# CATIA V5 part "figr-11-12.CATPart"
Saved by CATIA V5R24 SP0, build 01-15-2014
Part number: Part1
Bounding box of the stored display mesh (mm): x -10 to 5, y -10.258 to 7.91, z -1.851 to 2.054
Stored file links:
  D:\KAVITA\CATIA V5-6R2014 Project_ Kavita\CATIA V5-6R2014_partfiles\Partfiles\c11_catia_v5-6r2014_prt\figr-11-12.CATPart
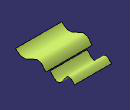
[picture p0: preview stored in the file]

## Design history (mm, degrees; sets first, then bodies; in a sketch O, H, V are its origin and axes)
Set1
  Sketch1 on yz-plane, origin (0, 0, 0), H (0, 1, 0), V (0, 0, 1)
    spline S1 through (-0.358, 0) (-3.1664, 2.0538) (-6.7822, 0.4079) (-10.2576, 1.6423)
    point P1 (-0.358, 0)
    coincidence: P1 H
  Extrude1: Element1 Sketch1, Lim1 5, Lim2 10, Direction yz-plane
  Sketch2 on yz-plane, origin (0, 0, 0), H (0, 1, 0), V (0, 0, 1)
    spline S1 through (0, 0) (3.5471, -1.4404) (5.7957, 1.2855) (7.9098, 0)
    point P1 (0, 0)
    point P2 (7.9098, 0)
    coincidence: P1 O, P2 H
  Extrude2: Element1 Sketch2, Lim1 4, Lim2 8, Direction yz-plane
Body1 (main body)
